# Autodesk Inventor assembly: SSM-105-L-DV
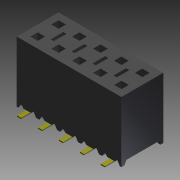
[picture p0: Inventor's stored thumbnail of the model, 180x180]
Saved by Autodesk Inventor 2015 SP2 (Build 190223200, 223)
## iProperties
Category: PARTsolutions
Company: SAMTEC
Created: 2015-08
Part Number: SSM-105-L-DV
Catalog Web Link: www.cadenas.de
Description: SSM Series-SSM Series - (2,54 mm) .100" Tiger Claw™ Surface Mount Socket
Vendor: SAMTEC
Document SubType Name: Assembly
Designer: PARTuser1
Manufacturer: SAMTEC
Mass: 0.392575 g
Surface Area: 7.21297 cm^2
Volume: 0.392575 cm^3
Density: 1 g/cm^3
PSOL_IDENT_0: {$CADENAS_DATA\23d-libs\samtec\modelling\ssm\ssm_asmtab.prj},242 {VTYP=3D},{STYP=ASSTAB},{NB=SSM-105
PSOL_IDENT_1: -L-DV},{LINA=SSM-105-L-DV},{NN=SSM Series},{DATE=15.05.2015 12:28:12},{GEOMDATE=24.10.2014 06:52:24}
PSOL_IDENT_2: ,{VERSION=},{LINEID=10},{LINESUBID=-1},{WBVAR=POS,ROW,PLOPT,BEOPT,LCOPT,POLOPT,AOPT,POPT,MOPT,KOPT,T
PSOL_IDENT_3: ROPT}  {NB=SSM-105-L-DV},{LINA=SSM-105-L-DV},{KT=DUMMY},{PN=SSM-105-L-DV},{SERIES=SSM},{POS=5},{POSP
PSOL_IDENT_4: N=05},{ROW=-DV},{ROWALG= '-SV','-SV - Single Vertical','-SH','-SH - Single Horizontal','-DH','-DH -
PSOL_IDENT_5: Double Horizontal','-DV','-DV - Double Vertical' },{PLOPT=-L},{PLOPTALG= '-S','-S - 30micro\" Select
PSOL_IDENT_6: ive Gold in Contact Area, Matte Tin on Tail','-L','-L - 10micro\" Light Selective Gold in Contact Ar
PSOL_IDENT_7: ea, Matte Tin on Tail','-T','-T - Matte Tin Contact and Tail (Non-standard option -  Please contact
PSOL_IDENT_8: SAMTEC)','-F','-F - 3micro\" Flash Selective Gold Contact, Matte Tin on Tail','-H','-H - 30micro\" H
PSOL_IDENT_9: eavy Gold in Contact Area, 3micro\" on Tail (Non-standard option -  Please contact SAMTEC)','-STL','
PSOL_IDENT_10: -STL - 30micro\" Selective Gold in Contact Area, Tin/Lead (90/10+/-5%) Tail (Non-standard option -
PSOL_IDENT_11: Please contact SAMTEC)','-SM','-SM - 30micro\" Selective Gold in Contact Area, Matte Tin on Tail (No
PSOL_IDENT_12: n-standard option -  Please contact SAMTEC)','-LM','-LM - 10micro\" Light Selective Gold in Contact
PSOL_IDENT_13: Area, Matte Tin Tail (Non-standard option -  Please contact SAMTEC)','-TM','-TM - Matte Tin Contact
PSOL_IDENT_14: and tail (Non-standard option -  Please contact SAMTEC)','-FM','-FM - 3micro\" Flash Selective Gold
PSOL_IDENT_15: in Contact Area, Matte Tin Tail (Non-standard option -  Please contact SAMTEC)' },{BEOPT=},{BEOPTALG=
PSOL_IDENT_16: '','Not Selected','-BE','-BE - Bottom Entry' },{LCOPT=},{LCOPTALG= '','Not Selected','-LC','-LC Loc
PSOL_IDENT_17: king Clip' },{POLOPT=},{POLOPTALG= '','Not Selected','001','001','002','002','003','003','004','004'
PSOL_IDENT_18: ,'005','005','006','006','007','007','008','008','009','009','010','010' },{POLOPTMAX=120},{POLOPTMA
PSOL_IDENT_19: X2='001','001','002','002','003','003','004','004','005','005','006','006','007','007','008','008','
PSOL_IDENT_20: 009','009','010','010'},{POLOPTPN=},{POLARIZE='001','001','002','002','003','003','004','004','005','
PSOL_IDENT_21: 005','006','006','007','007','008','008','009','009','010','010','011','011','012','012','013','013'
PSOL_IDENT_22: ,'014','014','015','015','016','016','017','017','018','018','019','019','020','020','021','021','02
PSOL_IDENT_23: 2','022','023','023','024','024','025','025','026','026','027','027','028','028','029','029','030','
PSOL_IDENT_24: 030','031','031','032','032','033','033','034','034','035','035','036','036','037','037','038','038'
PSOL_IDENT_25: ,'039','039','040','040','041','041','042','042','043','043','044','044','045','045','046','046','04
PSOL_IDENT_26: 7','047','048','048','049','049','050','050','051','051','052','052','053','053','054','054','055','
PSOL_IDENT_27: 055','056','056','057','057','058','058','059','059','060','060','061','061','062','062','063','063'
PSOL_IDENT_28: ,'064','064','065','065','066','066','067','067','068','068','069','069','070','070','071','071','07
PSOL_IDENT_29: 2','072','073','073','074','074','075','075','076','076','077','077','078','078','079','079','080','
PSOL_IDENT_30: 080'},{AOPT=},{AOPTALG= '','Not Selected','-A','-A - Alignment Pin (Non-standard option -  Please co
PSOL_IDENT_31: ntact SAMTEC)' },{POPT=},{POPTALG= '','Not Selected','-P','-P - Pick & Place Pad' },{MOPT=},{MOPTALG=
PSOL_IDENT_32: '','Not Selected','-M','-M - Metal Pick & Place Pad' },{KOPT=},{KOPTALG= '','Not Selected','-K','-K
PSOL_IDENT_33: - Polyimide Film Pad' },{TROPT=},{TROPALG= '','Not Selected','-TR','-TR - Tape & Reel'  },{PPATH=pa
PSOL_IDENT_34: rts/ssm_asmtpl.prj}
NN: SSM Series
NT: SSM Series - (2,54 mm) .100" Tiger Claw™ Surface Mount Socket
NB: SSM-105-L-DV
NBSYN: $PN.
LINA: SSM-105-L-DV
PN: SSM-105-L-DV
SERIES: SSM
POS: 5
ROW: -DV - Double Vertical
PLOPT: -L - 10micro" Light Selective Gold in Contact Area, Matte Tin on Tail
BEOPT: Not Selected
LCOPT: Not Selected
POLOPT: Not Selected
AOPT: Not Selected
POPT: Not Selected
MOPT: Not Selected
KOPT: Not Selected
TROPT: Not Selected
SUPPLIER: SAMTEC
ARTICLENO: SSM-105-L-DV
BOMINFO: SSM-105-L-DV
CREATOR: CADENAS GmbH
Title: SSM-105-L-DV
Author: Cadenas PARTsolutions
Comments: SSM Series - (2,54 mm) .100" Tiger Claw™ Surface Mount Socket
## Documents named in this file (3)
- D:\Tigers SVN\mechanik\2016\Inventor\Kaufteile\SSM-105-L-DV\SSM-105-L-DV.iam
- D:\Tigers SVN\mechanik\2016\Inventor\Kaufteile\SSM-105-L-DV\SSM-105-L-DV_body.ipt
- D:\Tigers SVN\mechanik\2016\Inventor\Kaufteile\SSM-105-L-DV\C-137-015.ipt
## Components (2 placed, 2 different names)
1. SSM-105-L-DV_body:1
2. C-137-015:1
